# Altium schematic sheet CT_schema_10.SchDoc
size 281 x 153 mm
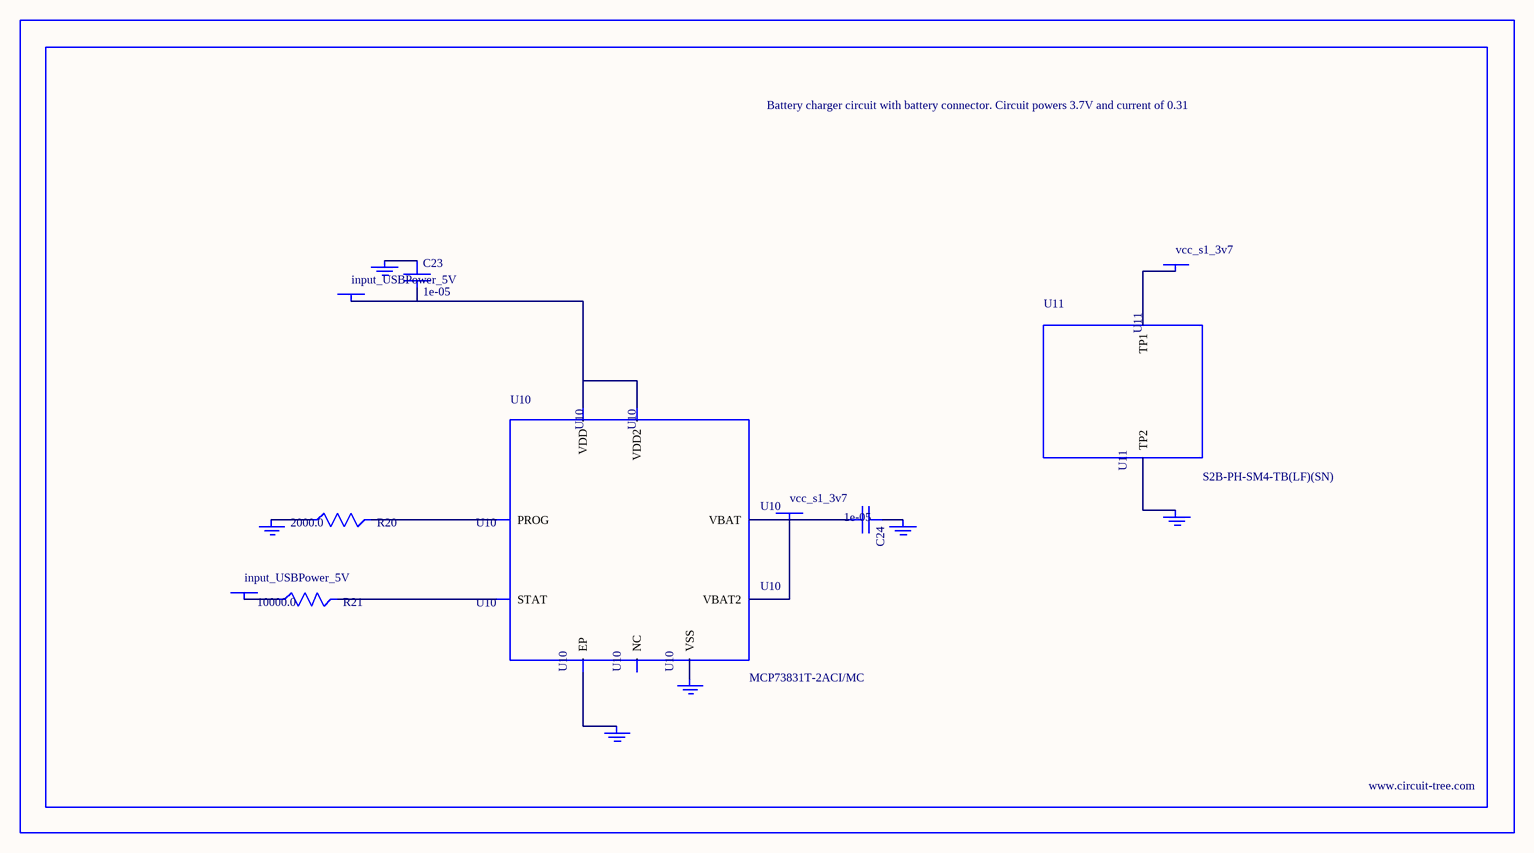
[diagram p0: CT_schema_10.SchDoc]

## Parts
BORDER9  (no value)
C23  1e-05  [C1206]
C24  1e-05  [C1206]
GND_INSTANCE_9_0  (no value)
GND_INSTANCE_9_1  (no value)
GND_INSTANCE_9_2  (no value)
GND_INSTANCE_9_3  (no value)
GND_INSTANCE_9_4  (no value)
GND_INSTANCE_9_5  (no value)
POWER_INSTANCE_9_0  input_USBPower_5V
POWER_INSTANCE_9_1  input_USBPower_5V
POWER_INSTANCE_9_2  vcc_s1_3v7
POWER_INSTANCE_9_3  vcc_s1_3v7
R20  2000.0  [R0603]
R21  10000.0  [R0603]
U10  MCP73831T-2ACI/MC  [DFN8_2X3MC]
U11  S2B-PH-SM4-TB(LF)(SN)  [JST-2-SMD]

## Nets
NetC23_1: C23.1 GND_INSTANCE_9_0.0(GND)
NetC23_2: C23.2 POWER_INSTANCE_9_0.0(PWR) U10.1(VDD) U10.2(VDD2)
NetC24_1: C24.1 GND_INSTANCE_9_1.0(GND)
NetC24_2: C24.2 POWER_INSTANCE_9_2.0(PWR) U10.3(VBAT) U10.4(VBAT2)
NetGND_INSTANCE_9_2_0: GND_INSTANCE_9_2.0(GND) R20.1
NetGND_INSTANCE_9_3_0: GND_INSTANCE_9_3.0(GND) U10.9(EP)
NetGND_INSTANCE_9_4_0: GND_INSTANCE_9_4.0(GND) U10.6(VSS)
NetGND_INSTANCE_9_5_0: GND_INSTANCE_9_5.0(GND) U11.2(TP2)
NetPOWER_INSTANCE_9_1_0: POWER_INSTANCE_9_1.0(PWR) R21.1
NetPOWER_INSTANCE_9_3_0: POWER_INSTANCE_9_3.0(PWR) U11.1(TP1)
NetR20_2: R20.2 U10.8(PROG)
NetR21_2: R21.2 U10.5(STAT)

Not connected (* = marked no-connect by the designer): U10 7(NC)

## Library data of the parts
BORDER9 = BORDER_PAGE9
C23 C24 = C1206C106K3RACTU
GND_INSTANCE_9_0-GND_INSTANCE_9_5 = GND
POWER_INSTANCE_9_0-POWER_INSTANCE_9_3 = PWR
R20 = RC0603JR-072KL
R21 = RC0603JR-0710KL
